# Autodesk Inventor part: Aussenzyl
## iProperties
Created: 2005-01
Part Number: Aussenzyl
Document SubType Name: Modeling
Designer: Administrator
Manufacturer: Standard
Standards Organization: Custom
Material: Aluminum-6061
Author: Administrator
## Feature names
1. Extrusion1
2. Extrusion2
3. Fillet1
